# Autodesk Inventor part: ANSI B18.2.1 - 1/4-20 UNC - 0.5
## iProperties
Comments: To add or edit properties for Autodesk Inventor files, use iProperties.
Created: 2004-09
Part Number: ANSI B18.2.1 - 1/4-20 UNC - 0.5
Vendor: Autodesk Inc.
Document SubType Name: Modeling
Designer: John Blackburn
Material: Default
Description: Hex Cap Screw
Standard: ANSI B18.2.1
Alert: To add or edit properties for Autodesk Inventor files, use iProperties.
Control State: 0
Master: False
Checked Out: False
Shininess: 64.0
Length Units: 11272
Angle Units: 11279
Time Units: 11290
Mass Units: 11286
Length Display Precision: 3
Angle Display Precision: 2
Compacted: True
EGR: 3
Classification: un/spsc 31161513
Density: 0.0
Volumn: 0.0
Area: 0.0
PropertySet Name: Model Information
Author: John Blackburn
Revision Number: 8
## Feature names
1. Body [Revolution]
2. Head [Extrusion]
3. Chamfer1 [Revolution]
4. Chamfer2
